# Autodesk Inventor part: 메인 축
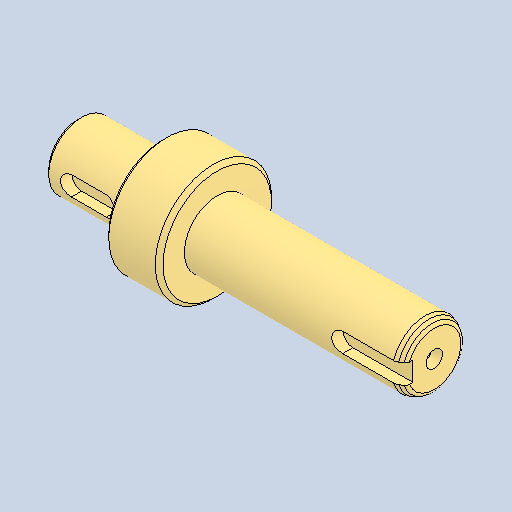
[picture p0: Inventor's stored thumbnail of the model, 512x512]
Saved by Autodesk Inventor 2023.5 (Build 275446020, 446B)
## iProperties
Created: 2026-07
Part Number: 메인 축
Material: 강철, 탄소
Document SubType Name: Modeling
Designer: mirae
Density: 7.85 g/cm^3
Appearance: 기본값
Author: jhkim
Revision Number: 1
Sending System: Autodesk Inventor 2027
Preprocessor: ST-DEVELOPER v20.1
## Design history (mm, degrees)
node "메인 축1"
node "솔리드2"
node "솔리드1"
